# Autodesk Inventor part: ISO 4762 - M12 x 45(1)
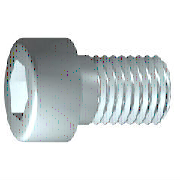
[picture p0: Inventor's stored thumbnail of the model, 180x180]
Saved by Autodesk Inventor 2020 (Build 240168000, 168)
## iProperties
Created: 2019-01
Part Number: ISO 4762 - M12 x 45(1)
Material: Nerezová ocel 440C
Description: Šroub s válcovou hlavou s vnitřním šestihranem
Document SubType Name: Modeling
Standard: ISO 4762
Designer: doma
Standard Revision: Fourth edition 2004-03-01
Standards Organization: ISO
Language: cs-CZ
Size Designation: M12 x 45
Categories: <MemberInstance><Categories><Category DisplayName="Spojovací materiál" InternalName="e4da775c-781d-43d5-af7c-5136215cf5a6" Mnemonic="FSTN"><Category DisplayName
Density: 7.75 g/cm^3
Appearance: Pololeštěná
IsCustomPart: 0
Author: doma
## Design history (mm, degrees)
sketch "Náčrt1"
  geometry: L1 (-2.667, 0)-(45, 0); L2 (45, 0)-(45, 6); L3 (45, 6)-(4.375, 6); L4 (4.375, 6)-(3.301, 6); L5 (3.301, 6)-(0, 6); L6 (0, 6)-(0, 9); L7 (0, 9)-(-12, 9); L8 (-12, 9)-(-12, 5.774); L9 (-12, 5.774)-(-6, 5.774); L10 (-6, 5.774)-(-2.667, 0); L11 (-23.4, 0)-(56.4, 0) reference; L12 (0, -1.8)-(0, 10.8) reference; L13 (4.375, 6)-(0, 6)
  constraints: 22 end point, 6 parallel, 2 collinear, 2 perpendicular, 1 horizontal, 1 point on line
  dimensions: "d1" = 40.625 distance from line of L3.end L2 (= GEL); "d2" = 1.07364 distance of L4.end L3.end (computed from GAL); "d3" = 12 distance between parallel lines of L8 L6 (= KOH); "d4" = 6 distance of L8.end L9.end (= INTI); "d5" = 60 deg angle of L10 L1; "d6" = 12 diameter of L3 L1 (= GD); "d7" = 12 diameter of L5 L1 (= BDM); "d8" = 11.54701 diameter of L9 L1 (= 1.1547 x SW); "d9" = 18 diameter of L7 L1 (= KOD); "d26" = 45 distance between parallel lines of L12 L2 (= NLG)
revolve "Těleso" sketch "Náčrt1" stored, may be unused: angle "d10" = 90 deg
sketch "Náčrt2"
  geometry: L1 (0, -12.6)-(0, 12.6) reference; L2 (-12.6, 0)-(12.6, 0) reference; L3 (5.774, 0)-(2.887, -5); L4 (2.887, -5)-(-2.887, -5); L5 (-2.887, -5)-(-5.774, 0); L6 (-5.774, 0)-(-2.887, 5); L7 (-2.887, 5)-(2.887, 5); L8 (2.887, 5)-(5.774, 0); 2 further points
  constraints: 12 end point, 1 coincident, 1 horizontal alignment, 1 point on line, 12 other
extrude "Drážka" join sketch "Náčrt2" stored distance "d11" = 10; taper "d12" = 0 deg
workplane "Work Plane1"
fillet "Fillet2" dims "d30" = 0.1 (= R)
body "Solid1"
fillet "Zaoblení1" dims "d17" = 1.2 (= RR)
feature "Závit" dims "d13" = 40.625 (= GEL), "d14" = 0
chamfer "Zkosení1" distance "d15" = 1.07354 (= -0.5 x SPD + 0.5 x GD); stored, may be unused: second distance "d16" = 1.07354 (= GUL), angle "d27" = 45 deg
other parameters: "GD" = 12 [user parameter; used in 2 equation terms], "NLG" = 45 [user parameter; used in 1 equation term], "GEL" = 40.625 [user parameter; used in 2 equation terms], "KOD" = 18 [user parameter; used in 1 equation term], "KOH" = 12 [user parameter; used in 1 equation term], "INTI" = 6 [user parameter; used in 1 equation term], "GAL" = 1.07354 (= 0.61345 x PTC) [user parameter; used in 1 equation term], "GUL" = 1.07354 (= 0.61345 x PTC) [user parameter; used in 1 equation term], "BDM" = 12 (= NND) [user parameter; used in 1 equation term], "RR" = 1.2 [user parameter; used in 1 equation term], "SPD" = 9.85293 (= NND - 1.2269 x PTC) [user parameter; used in 1 equation term], "d19" = 0, "d28" = 0, "d29" = 0, "R" = 0.1 [user parameter; used in 1 equation term], "TOA" = 30 deg [user parameter], "GD1" = 9.85293 (= THREADDIA - 1.2269 x PTC) [user parameter], "THREADDIA" = 12 [user parameter; used in 1 equation term], "FAWI" = 45 deg [user parameter], "TPU" = 5.71429 (computed from PTC) [user parameter], "PTC" = 1.75 [user parameter; used in 5 equation terms], "NND" = 12 [user parameter; used in 2 equation terms], "E0" = 11.55 (= 1.155 x SW) [user parameter]
